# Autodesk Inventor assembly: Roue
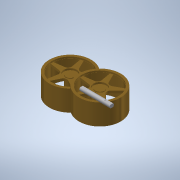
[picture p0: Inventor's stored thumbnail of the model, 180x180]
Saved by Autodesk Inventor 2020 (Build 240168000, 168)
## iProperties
Created: 2018-03
Part Number: Roue
Material: Générique
Document SubType Name: Assembly
Designer: Bruno
Author: Bruno
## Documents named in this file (4)
- C:\Users\bruno\Documents\1-Cours-2023-24\1STI2D\IT\robot-surveillance\Voiture-Inventor\Roue.iam
- C:\Users\bruno\Documents\1-Cours-2023-24\1STI2D\IT\robot-surveillance\Voiture-Inventor\Axe-moteur.ipt
- C:\Users\bruno\Documents\1-Cours-2023-24\1STI2D\IT\robot-surveillance\Voiture-Inventor\jante.ipt
- C:\Users\bruno\Documents\1-Cours-2023-24\1STI2D\IT\robot-surveillance\Voiture-Inventor\pneu.ipt
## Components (3 placed, 3 different names)
1. Axe-moteur:1 — Placage:1, Placage:2, Placage:3
2. jante:1 — Placage:1, Placage:2, Placage:3, Logement:1
3. pneu:1 — Logement:1
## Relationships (4: Mate 3, Insert 1)
- Placage:1 [Mate]: Axe-moteur:1 ↔ jante:1
- Placage:2 [Mate]: Axe-moteur:1 ↔ jante:1
- Placage:3 [Mate]: Axe-moteur:1 ↔ jante:1
- Logement:1 [Insert]: jante:1 ↔ pneu:1
